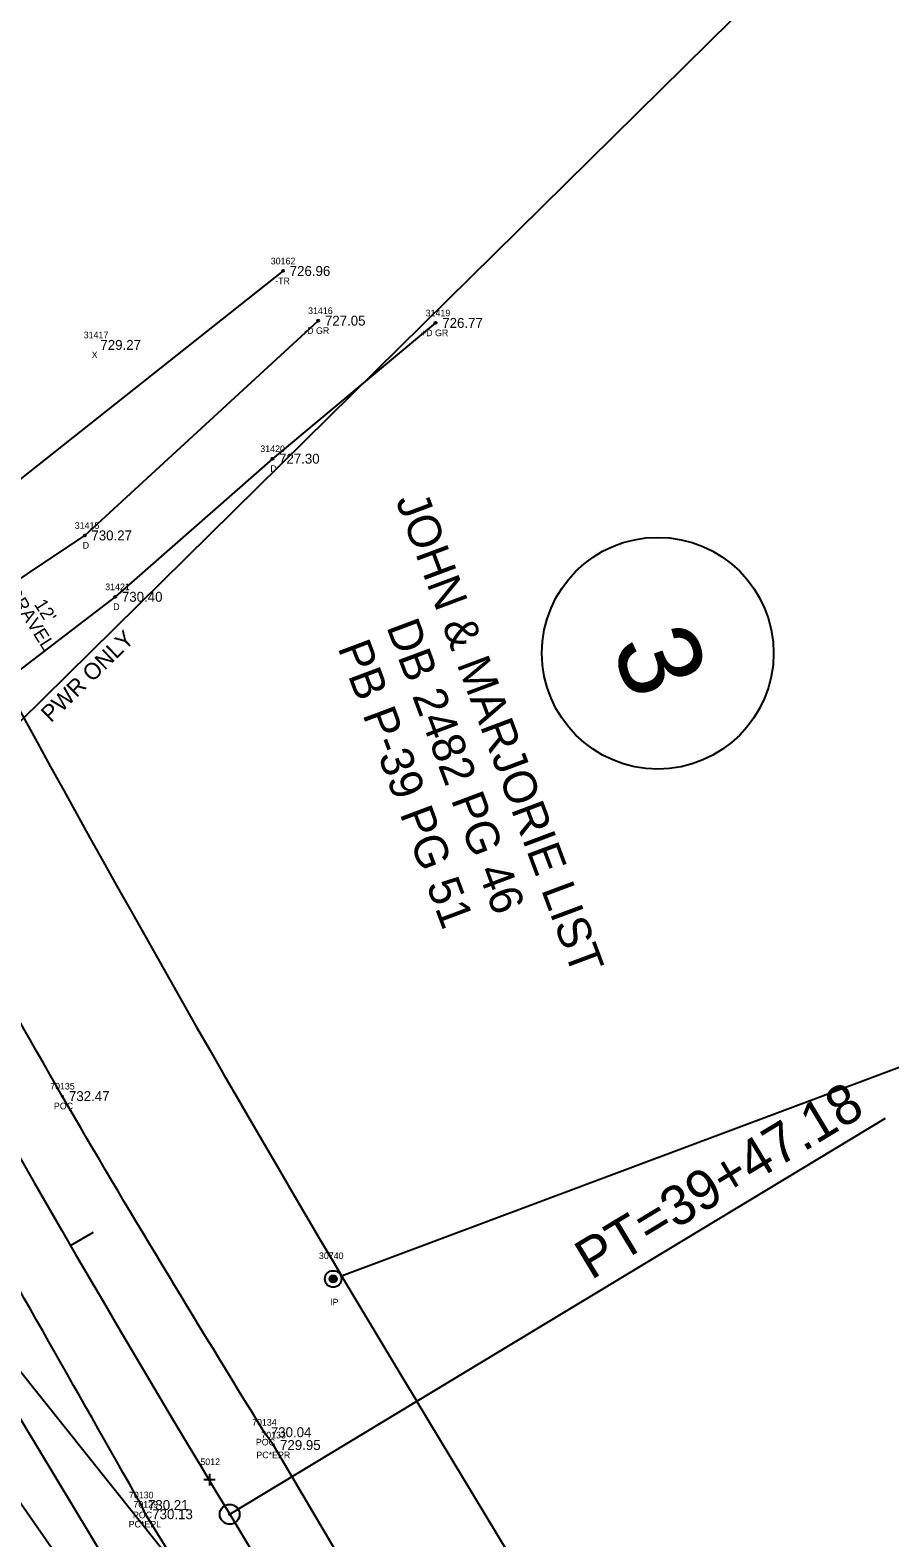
# Model space of a CAD drawing. Extents: x 1375131 to 1378678, y 999028 to 1004053.
# Drawn here: x 1376977.9 to 1377107.8, y 1002249 to 1002476.7 of the extents above; entities that cross this region are included whole.
import ezdxf

# ---------------------------------------------------------------- set-up
doc = ezdxf.new("R2010")
doc.units = 0
for name, color, linetype in [('Default', 7, 'Continuous'), ('RD_EX_Driveway', 7, 'Continuous'), ('RD_EX_Driveway_txCode', 7, 'Continuous'), ('RD_EX_DV_Prop', 7, 'Continuous'), ('RD_EX_DV_Prop_txCode', 7, 'Continuous'), ('RD_EX_DV_PropPin', 7, 'Continuous'), ('RD_EX_DV_TX_Prop(Owner ID)', 7, 'Continuous'), ('RD_EX_H2O', 7, 'Continuous'), ('RD_EX_Misc_txCode', 7, 'Continuous'), ('RD_EX_Road', 7, 'Continuous'), ('RD_EX_Road_txCode', 7, 'Continuous'), ('RD_EX_RW', 7, 'Continuous'), ('RD_EX_SU_Elec', 7, 'Continuous'), ('RD_EX_TX_Driveway_ELEV', 7, 'Continuous'), ('RD_EX_TX_Misc_ELEV', 7, 'Continuous'), ('RD_EX_TX_Road_ELEV', 7, 'Continuous'), ('RD_EX_TX_VEG_ELEV', 7, 'Continuous'), ('RD_EX_VEG', 7, 'Continuous'), ('RD_EX_VEG_txCode', 7, 'Continuous'), ('RD_HC_Cl', 7, 'Continuous'), ('RD_HC_Data', 7, 'Continuous'), ('RD_HC_Data_Tic', 7, 'Continuous'), ('RD_SMD_Locator', 7, 'Continuous'), ('RD_TX_Misc2', 7, 'Continuous'), ('RD_TX_Utilities', 7, 'Continuous')]:
    doc.layers.add(name, color=color, linetype=linetype)

msp = doc.modelspace()

# ---------------------------------------------------------------- linework, layer by layer
at = {"layer": 'Default'}
for p, q in [((1377005.04, 1002258.62), (1377005.04, 1002256.87)), ((1377005.92, 1002257.74), (1377004.17, 1002257.74))]:
    msp.add_line(p, q, dxfattribs=at)
at = {"layer": 'RD_EX_Driveway'}
for points in [[(1376960.83, 1002383.95), (1376961.45, 1002384.22), (1376968.84, 1002388.78), (1376986.2, 1002400.38), (1377021.48, 1002432.82)], [(1377039.21, 1002432.48), (1377014.55, 1002411.97), (1376990.81, 1002391.11), (1376968.15, 1002373.77), (1376967.2, 1002372.83)]]:
    msp.add_lwpolyline(points, dxfattribs=at)
at = {"layer": 'RD_EX_DV_Prop'}
msp.add_line((1377025, 1002288.53), (1377387.68, 1002424.34), dxfattribs=at)
at = {"layer": 'RD_EX_DV_PropPin'}
for p, q in [((1377023.21, 1002287.92), (1377023.21, 1002288.2)), ((1377023.23, 1002287.85), (1377023.23, 1002288.27)), ((1377023.26, 1002287.8), (1377023.26, 1002288.32)), ((1377023.28, 1002287.76), (1377023.28, 1002288.37)), ((1377023.31, 1002287.72), (1377023.31, 1002288.4)), ((1377023.33, 1002287.69), (1377023.33, 1002288.43)), ((1377023.36, 1002287.67), (1377023.36, 1002288.45)), ((1377023.38, 1002287.65), (1377023.38, 1002288.48)), ((1377023.41, 1002287.63), (1377023.41, 1002288.5)), ((1377023.43, 1002287.61), (1377023.43, 1002288.51)), ((1377023.46, 1002287.59), (1377023.46, 1002288.53)), ((1377023.48, 1002287.58), (1377023.48, 1002288.54)), ((1377023.51, 1002287.57), (1377023.51, 1002288.56)), ((1377023.53, 1002287.56), (1377023.53, 1002288.57)), ((1377023.56, 1002287.55), (1377023.56, 1002288.58)), ((1377023.58, 1002287.54), (1377023.58, 1002288.58)), ((1377023.61, 1002287.53), (1377023.61, 1002288.59)), ((1377023.63, 1002287.53), (1377023.63, 1002288.6)), ((1377023.66, 1002287.52), (1377023.66, 1002288.6)), ((1377023.68, 1002287.52), (1377023.68, 1002288.6)), ((1377023.71, 1002287.52), (1377023.71, 1002288.6)), ((1377023.73, 1002287.52), (1377023.73, 1002288.6)), ((1377023.76, 1002287.52), (1377023.76, 1002288.6)), ((1377023.78, 1002287.52), (1377023.78, 1002288.6)), ((1377023.81, 1002287.52), (1377023.81, 1002288.6)), ((1377023.83, 1002287.53), (1377023.83, 1002288.6)), ((1377023.86, 1002287.53), (1377023.86, 1002288.59)), ((1377023.88, 1002287.54), (1377023.88, 1002288.58)), ((1377023.91, 1002287.55), (1377023.91, 1002288.58)), ((1377023.93, 1002287.56), (1377023.93, 1002288.57)), ((1377023.96, 1002287.57), (1377023.96, 1002288.56)), ((1377023.98, 1002287.58), (1377023.98, 1002288.54)), ((1377024.01, 1002287.59), (1377024.01, 1002288.53)), ((1377024.03, 1002287.61), (1377024.03, 1002288.51)), ((1377024.06, 1002287.63), (1377024.06, 1002288.5)), ((1377024.08, 1002287.65), (1377024.08, 1002288.48)), ((1377024.11, 1002287.67), (1377024.11, 1002288.45)), ((1377024.13, 1002287.69), (1377024.13, 1002288.43)), ((1377024.16, 1002287.72), (1377024.16, 1002288.4)), ((1377024.18, 1002287.76), (1377024.18, 1002288.37)), ((1377024.21, 1002287.8), (1377024.21, 1002288.32)), ((1377024.23, 1002287.85), (1377024.23, 1002288.27)), ((1377024.26, 1002287.92), (1377024.26, 1002288.2))]:
    msp.add_line(p, q, dxfattribs=at)
for radius in [1.25, 0.543]:
    msp.add_circle((1377023.73, 1002288.06), radius, dxfattribs=at)
at = {"layer": 'RD_EX_DV_TX_Prop(Owner ID)'}
msp.add_circle((1377072.77, 1002382.59), 17.5, dxfattribs=at)
at = {"layer": 'RD_EX_H2O'}
msp.add_lwpolyline([(1377136.38, 1001999.34), (1377116.95, 1002033.41), (1377090.35, 1002075.98), (1377065.42, 1002117.59), (1377038.3, 1002163.03), (1377017.87, 1002196.37), (1376989.72, 1002244.93), (1376963.62, 1002288.23), (1376935.26, 1002334.03)], dxfattribs=at)
at = {"layer": 'RD_EX_Road'}
for points in [[(1377350.34, 1001708.26), (1377317.92, 1001758.89), (1377286.96, 1001809.89), (1377254.77, 1001863.4), (1377224.6, 1001914.86), (1377192.26, 1001967.36), (1377160.97, 1002019.84), (1377129.72, 1002070.66), (1377099.39, 1002121.71), (1377064.16, 1002179.08), (1377033.49, 1002231.09), (1377014.7, 1002262.97), (1377013.31, 1002264.91)], [(1377330.92, 1001696.38), (1377301.06, 1001747.92), (1377269.09, 1001800.22), (1377238.03, 1001851.8), (1377206.51, 1001905.09), (1377174.78, 1001956.21), (1377142.24, 1002010.21), (1377112.37, 1002059.86), (1377081.07, 1002112.14), (1377047.75, 1002166.27), (1377015.04, 1002220.7), (1376995.39, 1002252.52), (1376994.75, 1002253.91)]]:
    msp.add_lwpolyline(points, dxfattribs=at)
for points in [[(1377013.31, 1002264.91), (1376982.81, 1002315.68), (1376952.47, 1002370.34), (1376923.17, 1002424.32), (1376895.64, 1002480.03), (1376870.11, 1002535.05), (1376846.33, 1002588.86), (1376822.29, 1002645.03), (1376786.56, 1002736.46)], [(1376994.75, 1002253.91), (1376964.91, 1002306.46), (1376934.4, 1002359.99), (1376904.77, 1002415.49), (1376877.27, 1002471.51), (1376851.04, 1002526.89), (1376827.48, 1002581.62), (1376804.19, 1002637.82), (1376768.46, 1002728.84)]]:
    msp.add_spline(points, degree=3, dxfattribs=at)
at = {"layer": 'RD_EX_RW'}
msp.add_line((1377036.35, 1002269.57), (1377580.54, 1001368.57), dxfattribs=at)
for radius in [2767, 2833]:
    msp.add_arc((1379404.86, 1003700.11), radius, 200.26995, 211.13117, dxfattribs=at)
at = {"layer": 'RD_EX_SU_Elec'}
msp.add_line((1376932.6, 1002329.07), (1377119.53, 1002513.39), dxfattribs=at)
msp.add_lwpolyline([(1376932.6, 1002329.07), (1377163.28, 1002039.96), (1377247.04, 1001903.65)], dxfattribs=at)
at = {"layer": 'RD_EX_VEG'}
for points in [[(1377016.16, 1002440.33), (1376948.43, 1002386.71), (1376912.58, 1002489.62), (1376961.85, 1002505.13), (1376995.25, 1002514.98)], [(1376925.29, 1002323.56), (1376964.39, 1002271.55), (1376999.6, 1002220.98), (1377033.75, 1002161.52), (1377072.45, 1002098.21), (1377110.65, 1002037.08), (1377148.79, 1001977.33), (1377186.7, 1001917.17), (1377238.51, 1001843.58), (1377265.98, 1001789.91), (1377290.89, 1001746.87), (1377322.19, 1001689.75), (1377357.87, 1001632.38)]]:
    msp.add_lwpolyline(points, dxfattribs=at)
at = {"layer": 'RD_HC_Cl'}
msp.add_line((1377008.1, 1002252.51), (1377552.29, 1001351.51), dxfattribs=at)
msp.add_arc((1379404.86, 1003700.11), 2800, 200.26995, 211.13117, dxfattribs=at)
at = {"layer": 'RD_HC_Data'}
msp.add_line((1377008.1, 1002252.51), (1377107.15, 1002312.33), dxfattribs=at)
for radius in [1.5, 0.141]:
    msp.add_circle((1377008.1, 1002252.51), radius, dxfattribs=at)
at = {"layer": 'RD_HC_Data_Tic'}
msp.add_line((1376984.05, 1002293.1), (1376987.51, 1002295.11), dxfattribs=at)
at = {"layer": 'RD_SMD_Locator'}
for centre, radius in [((1377016.16, 1002440.33), 0.15), ((1377021.48, 1002432.82), 0.15), ((1377039.21, 1002432.48), 0.15), ((1377014.55, 1002411.97), 0.15), ((1376986.2, 1002400.38), 0.15), ((1376990.81, 1002391.11), 0.15), ((1376982.81, 1002315.68), 0.075), ((1377023.73, 1002288.06), 0.075), ((1377013.31, 1002264.91), 0.075), ((1377014.7, 1002262.97), 0.075), ((1376994.75, 1002253.91), 0.075), ((1376995.39, 1002252.52), 0.075)]:
    msp.add_circle(centre, radius, dxfattribs=at)

# ---------------------------------------------------------------- texts
at = {"layer": 'Default'}
msp.add_text('5012', height=1, dxfattribs=at).set_placement((1377003.66, 1002259.94))
at = {"layer": 'RD_EX_Driveway_txCode'}
for s, p in [('31416', (1377019.94, 1002433.82)), ('31419', (1377037.7, 1002433.48)), ('-D GR', (1377019.35, 1002430.82)), ('+D GR', (1377037, 1002430.48)), ('31420', (1377012.72, 1002412.97)), ('D', (1377014.25, 1002409.97)), ('31415', (1376984.69, 1002401.38)), ('D', (1376985.89, 1002398.38)), ('31421', (1376989.29, 1002392.11)), ('D', (1376990.5, 1002389.11))]:
    msp.add_text(s, height=1, dxfattribs=at).set_placement(p)
at = {"layer": 'RD_EX_DV_Prop_txCode'}
for s, p in [('30740', (1377021.58, 1002291.06)), ('30740', (1377021.58, 1002291.06)), ('IP', (1377023.26, 1002284.06)), ('IP', (1377023.26, 1002284.06))]:
    msp.add_text(s, height=1, dxfattribs=at).set_placement(p)
at = {"layer": 'RD_EX_DV_TX_Prop(Owner ID)'}
for s, height, p in [('JOHN & MARJORIE LIST', 5, (1377033.12, 1002405.69)), ('DB 2482 PG 46', 5, (1377031.72, 1002386.61)), ('3', 12.5, (1377065.68, 1002383.72)), ('PB P-39 PG 51', 5, (1377024.36, 1002383.44))]:
    msp.add_text(s, height=height, rotation=290.5003, dxfattribs=at).set_placement(p)
at = {"layer": 'RD_EX_Misc_txCode'}
for s, p in [('31417', (1376986.04, 1002430.16)), ('X', (1376987.24, 1002427.16))]:
    msp.add_text(s, height=1, dxfattribs=at).set_placement(p)
at = {"layer": 'RD_EX_Road_txCode'}
for s, p in [('70135', (1376980.97, 1002316.68)), ('POC', (1376981.54, 1002313.68)), ('70134', (1377011.48, 1002265.91)), ('POC', (1377012.05, 1002262.91)), ('70133', (1377012.87, 1002263.97)), ('PC*EPR', (1377012.12, 1002260.97)), ('70130', (1376992.87, 1002254.91)), ('70129', (1376993.55, 1002253.52)), ('POC', (1376993.48, 1002251.91)), ('PC*EPL', (1376992.83, 1002250.52))]:
    msp.add_text(s, height=1, dxfattribs=at).set_placement(p)
at = {"layer": 'RD_EX_TX_Driveway_ELEV'}
for s, p in [('727.05', (1377022.48, 1002432.07)), ('726.77', (1377040.21, 1002431.73)), ('727.30', (1377015.55, 1002411.22)), ('730.27', (1376987.2, 1002399.63)), ('730.40', (1376991.81, 1002390.36))]:
    msp.add_text(s, height=1.5, dxfattribs=at).set_placement(p)
at = {"layer": 'RD_EX_TX_Misc_ELEV'}
msp.add_text('729.27', height=1.5, dxfattribs=at).set_placement((1376988.56, 1002428.41))
at = {"layer": 'RD_EX_TX_Road_ELEV'}
for s, p in [('732.47', (1376983.81, 1002314.93)), ('730.04', (1377014.31, 1002264.16)), ('729.95', (1377015.7, 1002262.22)), ('730.21', (1376995.75, 1002253.16)), ('730.13', (1376996.39, 1002251.77))]:
    msp.add_text(s, height=1.5, dxfattribs=at).set_placement(p)
at = {"layer": 'RD_EX_TX_VEG_ELEV'}
msp.add_text('726.96', height=1.5, dxfattribs=at).set_placement((1377017.16, 1002439.58))
at = {"layer": 'RD_EX_VEG_txCode'}
for s, p in [('30162', (1377014.3, 1002441.33)), ('-TR', (1377014.96, 1002438.33))]:
    msp.add_text(s, height=1, dxfattribs=at).set_placement(p)
at = {"layer": 'RD_HC_Data'}
msp.add_text('PT=39+47.18', height=6, rotation=31.1312, dxfattribs=at).set_placement((1377062.7, 1002287.83))
at = {"layer": 'RD_TX_Misc2'}
for s, p in [('GRAVEL', (1376974.28, 1002391.96)), ("12'", (1376978.49, 1002389.98))]:
    msp.add_text(s, height=2, rotation=302.2952, dxfattribs=at).set_placement(p)
at = {"layer": 'RD_TX_Utilities'}
msp.add_text('PWR ONLY', height=2.5, rotation=44.2663, dxfattribs=at).set_placement((1376981.08, 1002372.02))

doc.saveas('drawing.dxf')
